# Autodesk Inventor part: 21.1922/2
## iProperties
Created: 2007-01
Part Number: 21.1922/2
Document SubType Name: Modeling
Designer: Andy Moles
Material: Steel
Mass: 14.1209 g
Surface Area: 12.6359 cm^2
Volume: 1.79884 cm^3
Density: 7.85 g/cm^3
Description: HINGE PIN 6 X 65
Vendor: V
Author: Andy Moles
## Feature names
1. Extrusion1
2. Chamfer1
3. Chamfer2
4. Extrusion2
5. Extrusion3
6. Circular Pattern1
